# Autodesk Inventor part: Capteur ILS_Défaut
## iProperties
Shininess: 64.0
Length Units: 11269
Angle Units: 11279
Time Units: 11290
Mass Units: 11283
Length Display Precision: 3
Angle Display Precision: 2
Compacted: True
Part Number: Capteur ILS_Défaut
Document SubType Name: Modeling
Created: 2006-01
Material: Par défaut
Designer: Fricot
Density: 0.0
Volumn: 0.0
Area: 0.0
PropertySet Name: Model Information
Control State: 0
Master: False
Checked Out: False
Author: Fricot
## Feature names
1. Base1
